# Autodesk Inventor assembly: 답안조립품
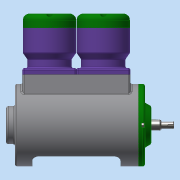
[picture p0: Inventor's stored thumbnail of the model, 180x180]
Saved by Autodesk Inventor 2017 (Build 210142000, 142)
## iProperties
Part Number: 답안조립품
Material: 일반
Document SubType Name: Assembly
Designer: Administrator
Author: Administrator
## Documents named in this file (16)
- C:\Users\Administrator\Desktop\620106V1005\답안조립품.iam
- C:\Users\Administrator\Desktop\620106V1005\너트 M4.ipt
- C:\Users\Administrator\Desktop\620106V1005\베어링 6303.ipt
- C:\Users\Administrator\Desktop\620106V1005\본체.ipt
- C:\Users\Administrator\Desktop\620106V1005\볼트 M4 x 12.ipt
- C:\Users\Administrator\Desktop\620106V1005\볼트 M5 x 20.ipt
- C:\Users\Administrator\Desktop\620106V1005\실린더.ipt
- C:\Users\Administrator\Desktop\620106V1005\실린더헤드.ipt
- C:\Users\Administrator\Desktop\620106V1005\앞커버.ipt
- C:\Users\Administrator\Desktop\620106V1005\오일 실 17 x 32 x 8.ipt
- C:\Users\Administrator\Desktop\620106V1005\육각 머리 볼트 M4 x 16.ipt
- C:\Users\Administrator\Desktop\620106V1005\커넥팅로드 엔드.ipt
- C:\Users\Administrator\Desktop\620106V1005\커넥팅로드.ipt
- C:\Users\Administrator\Desktop\620106V1005\크랭크축.ipt
- C:\Users\Administrator\Desktop\620106V1005\피스톤.ipt
- C:\Users\Administrator\Desktop\620106V1005\피스톤핀.ipt
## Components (4 placed, 2 different names)
1. 피스톤:1
2. 피스톤핀:1
3. 피스톤:2
4. 피스톤핀:2
